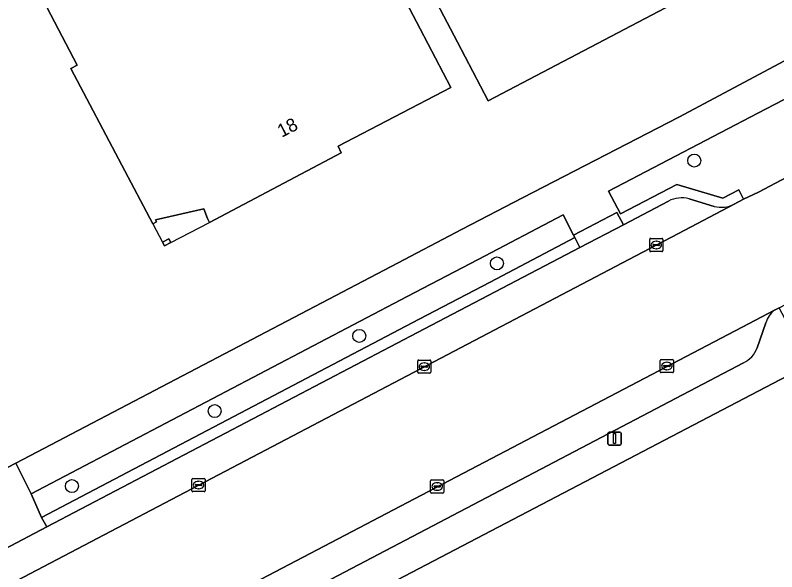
# Model space of a CAD drawing. Extents: x 157692 to 159674, y 381452 to 383291.
# Drawn here: x 158408.1 to 158465.6, y 381889.9 to 381931.9 of the extents above; entities that cross this region are included whole.
import ezdxf

# ---------------------------------------------------------------- set-up
doc = ezdxf.new("R2010")
doc.units = 0
for name, color, linetype in [('IMGEO_Berm_groen', 7, 'Continuous'), ('IMGEO_Boom', 7, 'Continuous'), ('IMGEO_Erf', 7, 'Continuous'), ('IMGEO_Groenvoorziening', 7, 'Continuous'), ('IMGEO_Kolk', 7, 'Continuous'), ('IMGEO_Lichtmast', 7, 'Continuous'), ('IMGEO_Pand', 7, 'Continuous'), ('IMGEO_Pand_nummerreeks', 7, 'Continuous'), ('IMGEO_Pand_overbouw', 7, 'Continuous'), ('IMGEO_Parkeervlak_open', 7, 'Continuous'), ('IMGEO_Rijbaan_lokaal_gesloten', 7, 'Continuous'), ('IMGEO_Voetpad_open', 7, 'Continuous')]:
    doc.layers.add(name, color=color, linetype=linetype)

msp = doc.modelspace()

# ---------------------------------------------------------------- linework, layer by layer
at = {"layer": 'IMGEO_Berm_groen'}
msp.add_lwpolyline([(158467.491, 381926.212), (158464.731, 381924.772), (158452.878, 381918.587), (158453.779, 381916.879), (158458.028, 381919.08), (158461.513, 381918.053), (158462.707, 381918.679), (158463.074, 381917.968), (158464.206, 381918.501), (158467.185, 381920.095), (158467.76, 381920.403), (158469.469, 381921.453), (158469.812, 381921.671)], close=True, dxfattribs=at)
at = {"layer": 'IMGEO_Boom'}
for centre in [(158459.35, 381920.894), (158444.454, 381913.132), (158434.063, 381907.663), (158423.151, 381901.984), (158412.378, 381896.328)]:
    msp.add_circle(centre, 0.489, dxfattribs=at)
at = {"layer": 'IMGEO_Erf'}
for points in [[(158449.553, 381969.324), (158452.267, 381964.153), (158458.66, 381967.509), (158466.327, 381952.898), (158467.509, 381953.533), (158470.115, 381948.52), (158466.816, 381946.721), (158470.569, 381939.46), (158443.791, 381925.407), (158441.467, 381929.835), (158426.965, 381957.47), (158445.126, 381967.001)], [(158420.83, 381964.842), (158438.656, 381930.841), (158440.978, 381926.412), (158432.483, 381921.989), (158432.709, 381921.465), (158422.751, 381916.231), (158422.603, 381916.515), (158422.325, 381917.239), (158418.688, 381916.418), (158418.767, 381916.268), (158418.482, 381916.117), (158416.15, 381920.541), (158412.303, 381927.838), (158412.772, 381928.099), (158399.375, 381953.65)], [(158419.212, 381914.733), (158419.69, 381914.984), (158419.84, 381914.701), (158419.361, 381914.45)]]:
    msp.add_lwpolyline(points, close=True, dxfattribs=at)
for points in [[(158217.316, 381839.906), (158270.263, 381825.792), (158286.558, 381834.286), (158292.839, 381837.605), (158310.343, 381846.755), (158316.773, 381850.116), (158323.795, 381853.778), (158342.759, 381863.76), (158347.941, 381866.531), (158348.596, 381866.872), (158358.563, 381872.057), (158364.635, 381875.26), (158392.478, 381889.849), (158400.12, 381893.872), (158401.991, 381894.865), (158408.14, 381898.064), (158436.465, 381912.9), (158441.823, 381915.706), (158446.378, 381918.092), (158458.186, 381924.156), (158466.161, 381928.413)], [(158416.142, 381764.387), (158441.975, 381777.745), (158461.034, 381788.171), (158500, 381809.488), (158502.7, 381810.965), (158517.225, 381818.911), (158502.7, 381848.284), (158500, 381853.744), (158473.086, 381908.164), (158468.009, 381905.516), (158408.054, 381874.141), (158402.221, 381871.049), (158376.84, 381857.708), (158371.263, 381854.776), (158369.169, 381853.676), (158368.188, 381853.16), (158362.112, 381850.005), (158326.367, 381831.251), (158320.477, 381828.192), (158299.749, 381817.336), (158293.835, 381814.232), (158289.45, 381811.892), (158283.086, 381808.549)]]:
    msp.add_lwpolyline(points, dxfattribs=at)
at = {"layer": 'IMGEO_Groenvoorziening'}
msp.add_lwpolyline([(158438.588, 381908.917), (158443.938, 381911.723), (158450.334, 381915.079), (158450.238, 381915.261), (158449.441, 381916.806), (158443.027, 381913.438), (158437.675, 381910.63), (158409.311, 381895.743), (158410.087, 381893.966)], close=True, dxfattribs=at)
at = {"layer": 'IMGEO_Kolk'}
for p, q in [((158456.057, 381915.021), (158456.909, 381915.021)), ((158455.982, 381914.095), (158455.982, 381914.947)), ((158456.241, 381914.515), (158456.241, 381914.527)), ((158456.679, 381914.478), (158456.281, 381914.478)), ((158456.284, 381914.564), (158456.682, 381914.564)), ((158456.47, 381914.801), (158456.495, 381914.801)), ((158456.725, 381914.527), (158456.725, 381914.515)), ((158456.983, 381914.947), (158456.983, 381914.095)), ((158456.909, 381914.021), (158456.057, 381914.021)), ((158456.493, 381914.241), (158456.468, 381914.241)), ((158438.548, 381905.841), (158439.4, 381905.841)), ((158456.778, 381904.962), (158456.778, 381905.814)), ((158456.853, 381905.888), (158457.705, 381905.888)), ((158457.779, 381905.814), (158457.779, 381904.962)), ((158438.473, 381904.915), (158438.473, 381905.767)), ((158438.732, 381905.335), (158438.732, 381905.347)), ((158439.17, 381905.298), (158438.772, 381905.298)), ((158438.775, 381905.384), (158439.173, 381905.384)), ((158438.961, 381905.621), (158438.986, 381905.621)), ((158439.216, 381905.347), (158439.216, 381905.335)), ((158439.474, 381905.767), (158439.474, 381904.915)), ((158457.037, 381905.382), (158457.037, 381905.394)), ((158457.475, 381905.345), (158457.077, 381905.345)), ((158457.08, 381905.431), (158457.478, 381905.431)), ((158457.266, 381905.668), (158457.291, 381905.668)), ((158457.521, 381905.394), (158457.521, 381905.382)), ((158439.4, 381904.841), (158438.548, 381904.841)), ((158438.984, 381905.061), (158438.959, 381905.061)), ((158457.705, 381904.888), (158456.853, 381904.888)), ((158457.289, 381905.108), (158457.264, 381905.108)), ((158421.437, 381895.982), (158421.437, 381896.834)), ((158421.512, 381896.908), (158422.364, 381896.908)), ((158421.925, 381896.688), (158421.95, 381896.688)), ((158422.438, 381896.834), (158422.438, 381895.982)), ((158439.444, 381895.872), (158439.444, 381896.724)), ((158439.519, 381896.798), (158440.371, 381896.798)), ((158440.445, 381896.724), (158440.445, 381895.872)), ((158421.696, 381896.402), (158421.696, 381896.414)), ((158422.134, 381896.365), (158421.736, 381896.365)), ((158421.739, 381896.451), (158422.137, 381896.451)), ((158421.948, 381896.128), (158421.923, 381896.128)), ((158422.18, 381896.414), (158422.18, 381896.402)), ((158439.703, 381896.292), (158439.703, 381896.304)), ((158440.141, 381896.255), (158439.743, 381896.255)), ((158439.746, 381896.341), (158440.144, 381896.341)), ((158439.932, 381896.578), (158439.957, 381896.578)), ((158440.187, 381896.304), (158440.187, 381896.292)), ((158422.364, 381895.908), (158421.512, 381895.908)), ((158440.371, 381895.798), (158439.519, 381895.798)), ((158439.955, 381896.018), (158439.93, 381896.018))]:
    msp.add_line(p, q, dxfattribs=at)
for points in [[(158456.057, 381915.021), (158456.909, 381915.021)], [(158455.982, 381914.095), (158455.982, 381914.947)], [(158456.983, 381914.947), (158456.983, 381914.095)], [(158456.909, 381914.021), (158456.057, 381914.021)], [(158438.548, 381905.841), (158439.4, 381905.841)], [(158456.778, 381904.962), (158456.778, 381905.814)], [(158456.853, 381905.888), (158457.705, 381905.888)], [(158457.779, 381905.814), (158457.779, 381904.962)], [(158438.473, 381904.915), (158438.473, 381905.767)], [(158439.474, 381905.767), (158439.474, 381904.915)], [(158439.4, 381904.841), (158438.548, 381904.841)], [(158457.705, 381904.888), (158456.853, 381904.888)], [(158421.437, 381895.982), (158421.437, 381896.834)], [(158421.512, 381896.908), (158422.364, 381896.908)], [(158422.438, 381896.834), (158422.438, 381895.982)], [(158439.444, 381895.872), (158439.444, 381896.724)], [(158439.519, 381896.798), (158440.371, 381896.798)], [(158440.445, 381896.724), (158440.445, 381895.872)], [(158422.364, 381895.908), (158421.512, 381895.908)], [(158440.371, 381895.798), (158439.519, 381895.798)]]:
    msp.add_lwpolyline(points, dxfattribs=at)
for centre, radius, start, end in [((158456.059, 381914.945), 0.0765, 91.55205, 178.44795), ((158456.059, 381914.945), 0.0765, 91.55205, 178.44795), ((158456.907, 381914.945), 0.0765, 1.55205, 88.44795), ((158456.907, 381914.945), 0.0765, 1.55205, 88.44795), ((158456.281, 381914.524), 0.0403, 85.87752, 175.75265), ((158456.278, 381914.514), 0.0366, 178.93798, 274.71019), ((158456.682, 381914.521), 0.043, 264.86636, 352.45326), ((158456.686, 381914.526), 0.0386, 1.73085, 96.63898), ((158456.059, 381914.097), 0.0765, 181.55205, 268.44795), ((158456.059, 381914.097), 0.0765, 181.55205, 268.44795), ((158456.907, 381914.097), 0.0765, 271.55205, 358.44795), ((158456.907, 381914.097), 0.0765, 271.55205, 358.44795), ((158438.55, 381905.765), 0.0765, 91.55205, 178.44795), ((158438.55, 381905.765), 0.0765, 91.55205, 178.44795), ((158439.398, 381905.765), 0.0765, 1.55205, 88.44795), ((158439.398, 381905.765), 0.0765, 1.55205, 88.44795), ((158456.855, 381905.812), 0.0765, 91.55205, 178.44795), ((158456.855, 381905.812), 0.0765, 91.55205, 178.44795), ((158457.703, 381905.812), 0.0765, 1.55205, 88.44795), ((158457.703, 381905.812), 0.0765, 1.55205, 88.44795), ((158438.772, 381905.344), 0.0403, 85.87752, 175.75265), ((158438.769, 381905.334), 0.0366, 178.93798, 274.71019), ((158439.173, 381905.341), 0.043, 264.86636, 352.45326), ((158439.177, 381905.346), 0.0386, 1.73085, 96.63898), ((158457.077, 381905.391), 0.0403, 85.87752, 175.75265), ((158457.074, 381905.381), 0.0366, 178.93798, 274.71019), ((158457.478, 381905.388), 0.043, 264.86636, 352.45326), ((158457.482, 381905.393), 0.0386, 1.73085, 96.63898), ((158438.55, 381904.917), 0.0765, 181.55205, 268.44795), ((158438.55, 381904.917), 0.0765, 181.55205, 268.44795), ((158439.398, 381904.917), 0.0765, 271.55205, 358.44795), ((158439.398, 381904.917), 0.0765, 271.55205, 358.44795), ((158456.855, 381904.964), 0.0765, 181.55205, 268.44795), ((158456.855, 381904.964), 0.0765, 181.55205, 268.44795), ((158457.703, 381904.964), 0.0765, 271.55205, 358.44795), ((158457.703, 381904.964), 0.0765, 271.55205, 358.44795), ((158421.514, 381896.832), 0.0765, 91.55205, 178.44795), ((158421.514, 381896.832), 0.0765, 91.55205, 178.44795), ((158422.362, 381896.832), 0.0765, 1.55205, 88.44795), ((158422.362, 381896.832), 0.0765, 1.55205, 88.44795), ((158439.521, 381896.722), 0.0765, 91.55205, 178.44795), ((158439.521, 381896.722), 0.0765, 91.55205, 178.44795), ((158440.369, 381896.722), 0.0765, 1.55205, 88.44795), ((158440.369, 381896.722), 0.0765, 1.55205, 88.44795), ((158421.736, 381896.411), 0.0403, 85.87752, 175.75265), ((158421.733, 381896.401), 0.0366, 178.93798, 274.71019), ((158422.137, 381896.408), 0.043, 264.86636, 352.45326), ((158422.141, 381896.413), 0.0386, 1.73085, 96.63898), ((158439.743, 381896.301), 0.0403, 85.87752, 175.75265), ((158439.74, 381896.291), 0.0366, 178.93798, 274.71019), ((158440.144, 381896.298), 0.043, 264.86636, 352.45326), ((158440.148, 381896.303), 0.0386, 1.73085, 96.63898), ((158421.514, 381895.984), 0.0765, 181.55205, 268.44795), ((158421.514, 381895.984), 0.0765, 181.55205, 268.44795), ((158422.362, 381895.984), 0.0765, 271.55205, 358.44795), ((158422.362, 381895.984), 0.0765, 271.55205, 358.44795), ((158439.521, 381895.874), 0.0765, 181.55205, 268.44795), ((158439.521, 381895.874), 0.0765, 181.55205, 268.44795), ((158440.369, 381895.874), 0.0765, 271.55205, 358.44795), ((158440.369, 381895.874), 0.0765, 271.55205, 358.44795)]:
    msp.add_arc(centre, radius, start, end, dxfattribs=at)
for centre, major_axis, ratio, start_param, end_param in [((158456.469, 381914.521), (-0.387, 0.002), 0.722429, 4.712389, 7.853982), ((158456.494, 381914.521), (-0.39, 0.002), 0.717154, 1.570796, 4.712389), ((158438.96, 381905.341), (-0.387, 0.002), 0.722429, 4.712389, 7.853982), ((158438.985, 381905.341), (-0.39, 0.002), 0.717154, 1.570796, 4.712389), ((158457.265, 381905.388), (-0.387, 0.002), 0.722429, 4.712389, 7.853982), ((158457.29, 381905.388), (-0.39, 0.002), 0.717154, 1.570796, 4.712389), ((158421.924, 381896.408), (-0.387, 0.002), 0.722429, 4.712389, 7.853982), ((158421.949, 381896.408), (-0.39, 0.002), 0.717154, 1.570796, 4.712389), ((158439.931, 381896.298), (-0.387, 0.002), 0.722429, 4.712389, 7.853982), ((158439.956, 381896.298), (-0.39, 0.002), 0.717154, 1.570796, 4.712389)]:
    msp.add_ellipse(centre, major_axis=major_axis, ratio=ratio, start_param=start_param, end_param=end_param, dxfattribs=at)
at = {"layer": 'IMGEO_Lichtmast'}
for p, q in [((158452.834, 381899.51), (158452.834, 381900.31)), ((158452.834, 381900.31), (158452.834, 381899.51)), ((158452.934, 381900.41), (158453.724, 381900.41)), ((158453.724, 381900.41), (158452.934, 381900.41)), ((158453.824, 381900.31), (158453.824, 381899.51)), ((158453.824, 381899.51), (158453.824, 381900.31)), ((158453.724, 381899.41), (158452.934, 381899.41)), ((158452.934, 381899.41), (158453.724, 381899.41))]:
    msp.add_line(p, q, dxfattribs=at)
msp.add_lwpolyline([(158453.254, 381900.285), (158453.404, 381900.285), (158453.404, 381899.535), (158453.254, 381899.535), (158453.254, 381900.285)], dxfattribs=at)
for centre, start, end in [((158452.934, 381900.31), 90, 180), ((158452.934, 381900.31), 90, 180), ((158453.724, 381900.31), 0, 90), ((158453.724, 381900.31), 360, 90), ((158452.934, 381899.51), 180, 270), ((158452.934, 381899.51), 180, 270), ((158453.724, 381899.51), 270, 0), ((158453.724, 381899.51), 270, 0)]:
    msp.add_arc(centre, 0.1, start, end, dxfattribs=at)
at = {"layer": 'IMGEO_Pand'}
for points in [[(158445.126, 381967.001), (158426.965, 381957.47), (158441.467, 381929.835), (158443.791, 381925.407), (158470.569, 381939.46), (158466.816, 381946.721), (158470.115, 381948.52), (158467.509, 381953.533), (158466.327, 381952.898), (158458.66, 381967.509), (158452.267, 381964.153), (158449.553, 381969.324)], [(158418.482, 381916.117), (158418.767, 381916.268), (158418.688, 381916.418), (158422.325, 381917.239), (158422.603, 381916.515), (158422.751, 381916.231), (158432.709, 381921.465), (158432.483, 381921.989), (158440.978, 381926.412), (158438.656, 381930.841), (158420.83, 381964.842), (158399.375, 381953.65), (158412.772, 381928.099), (158412.303, 381927.838), (158416.15, 381920.541)], [(158419.212, 381914.733), (158419.361, 381914.45), (158419.84, 381914.701), (158419.69, 381914.984)]]:
    msp.add_lwpolyline(points, close=True, dxfattribs=at)
at = {"layer": 'IMGEO_Pand_overbouw'}
msp.add_lwpolyline([(158419.212, 381914.733), (158419.69, 381914.984), (158419.84, 381914.701), (158422.751, 381916.231), (158422.603, 381916.515), (158422.325, 381917.239), (158418.688, 381916.418), (158418.767, 381916.268), (158418.482, 381916.117)], close=True, dxfattribs=at)
at = {"layer": 'IMGEO_Parkeervlak_open'}
for points in [[(158460.855, 381917.436), (158458.954, 381918.012)], [(158457.404, 381917.836), (158454, 381916.055), (158450.723, 381914.341), (158444.327, 381910.99), (158438.977, 381908.187), (158410.471, 381893.25), (158404.483, 381890.119), (158402.628, 381889.151), (158394.949, 381885.105), (158367.135, 381870.529), (158361.052, 381867.333), (158352.126, 381862.671), (158343.994, 381858.396), (158326.305, 381849.121), (158319.191, 381845.384), (158295.421, 381832.972), (158289.047, 381829.577), (158275.611, 381822.585), (158273.839, 381821.727), (158272.432, 381821.141), (158272.056, 381820.902), (158271.811, 381820.664), (158269.983, 381818.259)], [(158456.473, 381914.515), (158458.149, 381915.386), (158462.356, 381917.596)], [(158275.635, 381819.726), (158303.732, 381834.411), (158354.339, 381860.942), (158456.473, 381914.515)], [(158465.398, 381909.602), (158462.964, 381908.32), (158340.401, 381844.12), (158287.161, 381816.195)], [(158464.084, 381906.76), (158464.741, 381908.642)], [(158292.185, 381815.989), (158292.781, 381816.313), (158298.654, 381819.389), (158319.401, 381830.234), (158325.276, 381833.312), (158361.043, 381852.051), (158367.101, 381855.247), (158370.176, 381856.864), (158375.752, 381859.796), (158401.117, 381873.133), (158406.97, 381876.204), (158463.062, 381905.633)]]:
    msp.add_lwpolyline(points, dxfattribs=at)
for centre, radius, start, end in [((158458.411, 381915.88), 2.2, 75.71429, 117.24191), ((158461.4, 381919.442), 2.079, 254.7964, 297.37261), ((158466.671, 381908.026), 2.026, 128.92914, 162.29733), ((158462.277, 381907.372), 1.908, 294.29896, 341.29553)]:
    msp.add_arc(centre, radius, start, end, dxfattribs=at)
at = {"layer": 'IMGEO_Rijbaan_lokaal_gesloten'}
for points in [[(158462.964, 381908.32), (158465.398, 381909.602), (158465.751, 381909.788), (158471.08, 381912.561), (158472.817, 381913.475), (158469.812, 381921.671), (158469.469, 381921.453), (158467.76, 381920.403), (158467.185, 381920.095), (158464.206, 381918.501), (158463.074, 381917.968), (158462.356, 381917.596), (158458.149, 381915.386), (158456.473, 381914.515), (158354.339, 381860.942), (158303.732, 381834.411), (158275.635, 381819.726)], [(158280.869, 381812.874), (158287.161, 381816.195), (158340.401, 381844.12), (158462.964, 381908.32)]]:
    msp.add_lwpolyline(points, dxfattribs=at)
at = {"layer": 'IMGEO_Voetpad_open'}
for points in [[(158462.356, 381917.596), (158463.074, 381917.968), (158462.707, 381918.679), (158461.513, 381918.053), (158458.028, 381919.08), (158453.779, 381916.879), (158452.878, 381918.587), (158464.731, 381924.772), (158467.491, 381926.212), (158469.812, 381921.671), (158471.887, 381923.236), (158469.776, 381927.407), (158478.297, 381931.776)], [(158466.161, 381928.413), (158458.186, 381924.156), (158446.378, 381918.092), (158441.823, 381915.706), (158436.465, 381912.9), (158408.14, 381898.064), (158409.311, 381895.743), (158437.675, 381910.63), (158443.027, 381913.438), (158449.441, 381916.806), (158450.238, 381915.261), (158453.515, 381916.975), (158454, 381916.055), (158457.404, 381917.836)], [(158458.954, 381918.012), (158460.855, 381917.436)], [(158463.062, 381905.633), (158406.97, 381876.204), (158408.054, 381874.141), (158468.009, 381905.516), (158465.751, 381909.788), (158465.398, 381909.602)], [(158464.741, 381908.642), (158464.084, 381906.76)]]:
    msp.add_lwpolyline(points, dxfattribs=at)
for points in [[(158450.723, 381914.341), (158454, 381916.055), (158453.515, 381916.975), (158450.238, 381915.261), (158450.334, 381915.079)], [(158438.977, 381908.187), (158444.327, 381910.99), (158450.723, 381914.341), (158450.334, 381915.079), (158443.938, 381911.723), (158438.588, 381908.917), (158410.087, 381893.966), (158410.471, 381893.25)], [(158404.095, 381890.853), (158404.483, 381890.119), (158410.471, 381893.25), (158410.087, 381893.966), (158409.311, 381895.743), (158408.14, 381898.064), (158401.991, 381894.865), (158403.191, 381892.543)]]:
    msp.add_lwpolyline(points, close=True, dxfattribs=at)
for centre, radius, start, end in [((158458.411, 381915.88), 2.2, 75.71429, 117.24191), ((158461.4, 381919.442), 2.079, 254.7964, 297.37261), ((158466.671, 381908.026), 2.026, 128.92914, 162.29733), ((158462.277, 381907.372), 1.908, 294.29896, 341.29553)]:
    msp.add_arc(centre, radius, start, end, dxfattribs=at)

# ---------------------------------------------------------------- texts
at = {"layer": 'IMGEO_Pand_nummerreeks'}
msp.add_text('18', height=1, rotation=27.50416, dxfattribs=at).set_placement((158428.21, 381922.606))

doc.saveas('drawing.dxf')
